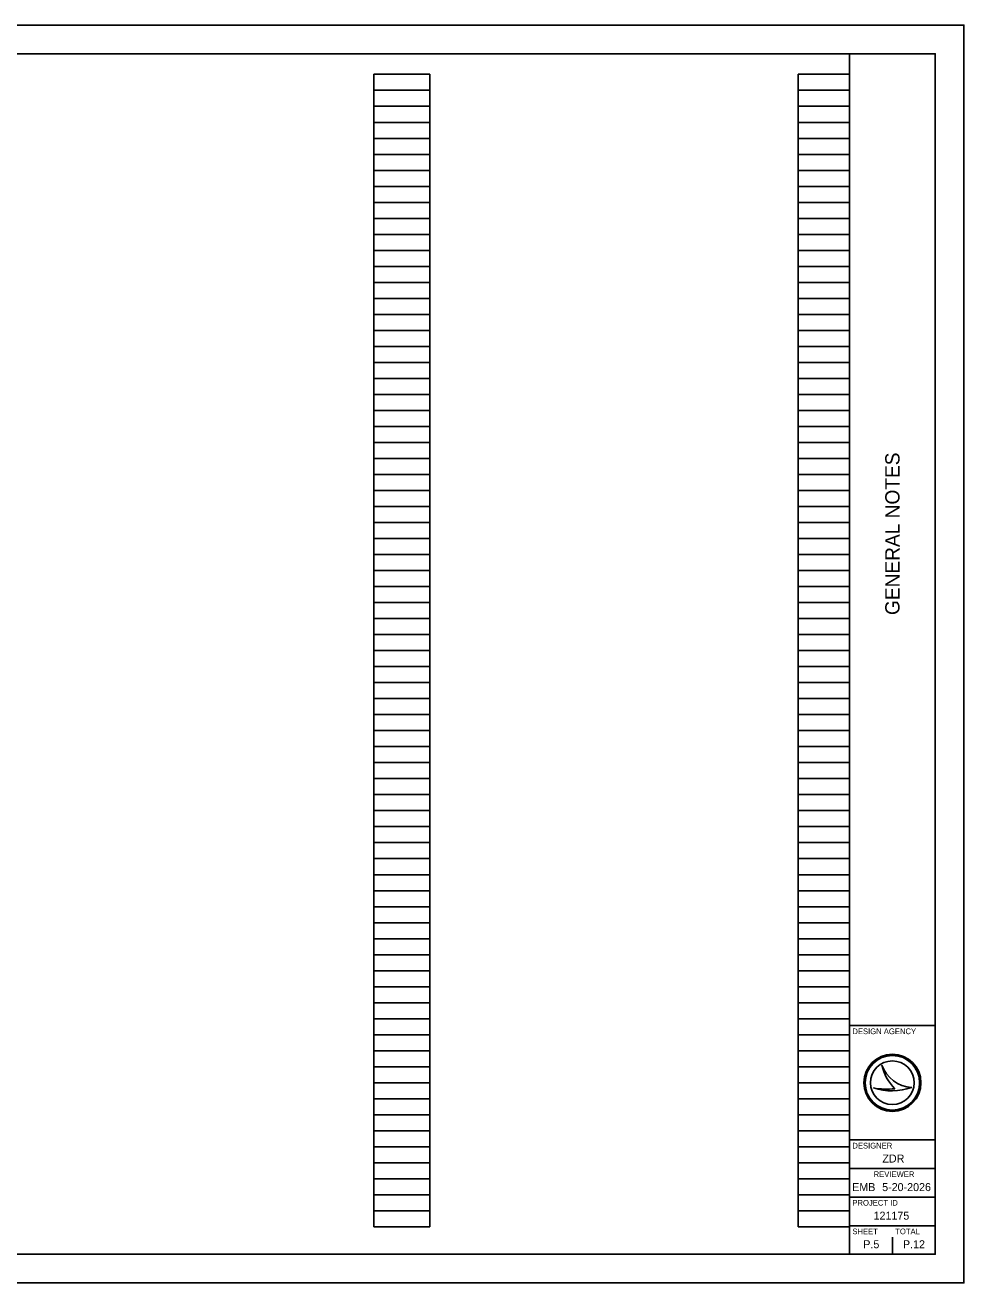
# Model space of a CAD drawing. Extents: x 0 to 34, y 0 to 22.
# Drawn here: x 17.58 to 34, y 0 to 22 of the extents above; entities that cross this region are included whole.
import ezdxf

# ---------------------------------------------------------------- set-up
doc = ezdxf.new("R2010")
doc.units = 0
for name, color, linetype in [('SH_Border', 7, 'Continuous'), ('SH_Cut_Line', 7, 'Continuous'), ('SH_Data', 7, 'Continuous')]:
    doc.layers.add(name, color=color, linetype=linetype)

msp = doc.modelspace()

# ---------------------------------------------------------------- linework, layer by layer
at = {"layer": 'SH_Border'}
for p, q in [((32, 0.5), (32, 21.5)), ((32, 4.5), (33.5, 4.5)), ((32, 2.5), (33.5, 2.5)), ((32, 2), (33.5, 2)), ((32, 1.5), (33.5, 1.5)), ((32, 1), (33.5, 1))]:
    msp.add_line(p, q, dxfattribs=at)
msp.add_lwpolyline([(1.5, 21.5), (33.5, 21.5), (33.5, 0.5), (1.5, 0.5)], close=True, dxfattribs=at)
at = {"layer": 'SH_Cut_Line'}
msp.add_lwpolyline([(0, 0), (34, 0), (34, 22), (0, 22)], close=True, dxfattribs=at)
at = {"layer": 'SH_Data'}
for p, q in [((23.68, 0.98), (23.68, 21.14)), ((23.68, 21.14), (24.66, 21.14)), ((24.66, 0.98), (24.66, 21.14)), ((31.1, 0.98), (31.1, 21.14)), ((31.1, 21.14), (32, 21.14)), ((32, 0.98), (32, 21.14)), ((23.68, 20.86), (24.66, 20.86)), ((31.1, 20.86), (32, 20.86)), ((23.68, 20.58), (24.66, 20.58)), ((31.1, 20.58), (32, 20.58)), ((23.68, 20.3), (24.66, 20.3)), ((31.1, 20.3), (32, 20.3)), ((23.68, 20.02), (24.66, 20.02)), ((31.1, 20.02), (32, 20.02)), ((23.68, 19.74), (24.66, 19.74)), ((31.1, 19.74), (32, 19.74)), ((23.68, 19.46), (24.66, 19.46)), ((31.1, 19.46), (32, 19.46)), ((23.68, 19.18), (24.66, 19.18)), ((31.1, 19.18), (32, 19.18)), ((23.68, 18.9), (24.66, 18.9)), ((31.1, 18.9), (32, 18.9)), ((23.68, 18.62), (24.66, 18.62)), ((31.1, 18.62), (32, 18.62)), ((23.68, 18.34), (24.66, 18.34)), ((31.1, 18.34), (32, 18.34)), ((23.68, 18.06), (24.66, 18.06)), ((31.1, 18.06), (32, 18.06)), ((23.68, 17.78), (24.66, 17.78)), ((31.1, 17.78), (32, 17.78)), ((23.68, 17.5), (24.66, 17.5)), ((31.1, 17.5), (32, 17.5)), ((23.68, 17.22), (24.66, 17.22)), ((31.1, 17.22), (32, 17.22)), ((23.68, 16.94), (24.66, 16.94)), ((31.1, 16.94), (32, 16.94)), ((23.68, 16.66), (24.66, 16.66)), ((31.1, 16.66), (32, 16.66)), ((23.68, 16.38), (24.66, 16.38)), ((31.1, 16.38), (32, 16.38)), ((23.68, 16.1), (24.66, 16.1)), ((31.1, 16.1), (32, 16.1)), ((23.68, 15.82), (24.66, 15.82)), ((31.1, 15.82), (32, 15.82)), ((23.68, 15.54), (24.66, 15.54)), ((31.1, 15.54), (32, 15.54)), ((23.68, 15.26), (24.66, 15.26)), ((31.1, 15.26), (32, 15.26)), ((23.68, 14.98), (24.66, 14.98)), ((31.1, 14.98), (32, 14.98)), ((23.68, 14.7), (24.66, 14.7)), ((31.1, 14.7), (32, 14.7)), ((23.68, 14.42), (24.66, 14.42)), ((31.1, 14.42), (32, 14.42)), ((23.68, 14.14), (24.66, 14.14)), ((31.1, 14.14), (32, 14.14)), ((23.68, 13.86), (24.66, 13.86)), ((31.1, 13.86), (32, 13.86)), ((23.68, 13.58), (24.66, 13.58)), ((31.1, 13.58), (32, 13.58)), ((23.68, 13.3), (24.66, 13.3)), ((31.1, 13.3), (32, 13.3)), ((23.68, 13.02), (24.66, 13.02)), ((31.1, 13.02), (32, 13.02)), ((23.68, 12.74), (24.66, 12.74)), ((31.1, 12.74), (32, 12.74)), ((23.68, 12.46), (24.66, 12.46)), ((31.1, 12.46), (32, 12.46)), ((23.68, 12.18), (24.66, 12.18)), ((31.1, 12.18), (32, 12.18)), ((23.68, 11.9), (24.66, 11.9)), ((31.1, 11.9), (32, 11.9)), ((23.68, 11.62), (24.66, 11.62)), ((31.1, 11.62), (32, 11.62)), ((23.68, 11.34), (24.66, 11.34)), ((31.1, 11.34), (32, 11.34)), ((23.68, 11.06), (24.66, 11.06)), ((31.1, 11.06), (32, 11.06)), ((23.68, 10.78), (24.66, 10.78)), ((31.1, 10.78), (32, 10.78)), ((23.68, 10.5), (24.66, 10.5)), ((31.1, 10.5), (32, 10.5)), ((23.68, 10.22), (24.66, 10.22)), ((31.1, 10.22), (32, 10.22)), ((23.68, 9.94), (24.66, 9.94)), ((31.1, 9.94), (32, 9.94)), ((23.68, 9.66), (24.66, 9.66)), ((31.1, 9.66), (32, 9.66)), ((23.68, 9.38), (24.66, 9.38)), ((31.1, 9.38), (32, 9.38)), ((23.68, 9.1), (24.66, 9.1)), ((31.1, 9.1), (32, 9.1)), ((23.68, 8.82), (24.66, 8.82)), ((31.1, 8.82), (32, 8.82)), ((23.68, 8.54), (24.66, 8.54)), ((31.1, 8.54), (32, 8.54)), ((23.68, 8.26), (24.66, 8.26)), ((31.1, 8.26), (32, 8.26)), ((23.68, 7.98), (24.66, 7.98)), ((31.1, 7.98), (32, 7.98)), ((23.68, 7.7), (24.66, 7.7)), ((31.1, 7.7), (32, 7.7)), ((23.68, 7.42), (24.66, 7.42)), ((31.1, 7.42), (32, 7.42)), ((23.68, 7.14), (24.66, 7.14)), ((31.1, 7.14), (32, 7.14)), ((23.68, 6.86), (24.66, 6.86)), ((31.1, 6.86), (32, 6.86)), ((23.68, 6.58), (24.66, 6.58)), ((31.1, 6.58), (32, 6.58)), ((23.68, 6.3), (24.66, 6.3)), ((31.1, 6.3), (32, 6.3)), ((23.68, 6.02), (24.66, 6.02)), ((31.1, 6.02), (32, 6.02)), ((23.68, 5.74), (24.66, 5.74)), ((31.1, 5.74), (32, 5.74)), ((23.68, 5.46), (24.66, 5.46)), ((31.1, 5.46), (32, 5.46)), ((23.68, 5.18), (24.66, 5.18)), ((31.1, 5.18), (32, 5.18)), ((23.68, 4.9), (24.66, 4.9)), ((31.1, 4.9), (32, 4.9)), ((23.68, 4.62), (24.66, 4.62)), ((31.1, 4.62), (32, 4.62)), ((23.68, 4.34), (24.66, 4.34)), ((31.1, 4.34), (32, 4.34)), ((23.68, 4.06), (24.66, 4.06)), ((31.1, 4.06), (32, 4.06)), ((23.68, 3.78), (24.66, 3.78)), ((31.1, 3.78), (32, 3.78)), ((32.567, 3.81), (32.567, 3.81)), ((23.68, 3.5), (24.66, 3.5)), ((31.1, 3.5), (32, 3.5)), ((32.417, 3.41), (32.417, 3.41)), ((32.75, 3.5), (32.75, 3.5)), ((33.087, 3.419), (33.087, 3.419)), ((23.68, 3.22), (24.66, 3.22)), ((31.1, 3.22), (32, 3.22)), ((23.68, 2.94), (24.66, 2.94)), ((31.1, 2.94), (32, 2.94)), ((23.68, 2.66), (24.66, 2.66)), ((31.1, 2.66), (32, 2.66)), ((23.68, 2.38), (24.66, 2.38)), ((31.1, 2.38), (32, 2.38)), ((23.68, 2.1), (24.66, 2.1)), ((31.1, 2.1), (32, 2.1)), ((23.68, 1.82), (24.66, 1.82)), ((31.1, 1.82), (32, 1.82)), ((23.68, 1.54), (24.66, 1.54)), ((31.1, 1.54), (32, 1.54)), ((23.68, 1.26), (24.66, 1.26)), ((31.1, 1.26), (32, 1.26)), ((23.68, 0.98), (24.66, 0.98)), ((31.1, 0.98), (32, 0.98)), ((32.375, 0.675), (32.375, 0.675)), ((32.75, 0.5), (32.75, 0.8))]:
    msp.add_line(p, q, dxfattribs=at)
for radius in [0.5, 0.477, 0.477, 0.382]:
    msp.add_circle((32.75, 3.5), radius, dxfattribs=at)
for centre, radius, start, end in [((33.116, 3.998), 0.58, 198.9257, 198.9319), ((33.347, 3.97), 0.796, 191.6379, 191.6421), ((33.116, 3.998), 0.58, 198.9319, 267.1657), ((33.347, 3.97), 0.796, 191.6421, 226.0947), ((32.739, 4.37), 1.013, 251.4576, 290.0832), ((32.648, 4.654), 1.266, 259.4964, 259.4995), ((32.739, 4.37), 1.013, 251.4527, 251.4576), ((32.648, 4.654), 1.266, 259.4995, 276.6672)]:
    msp.add_arc(centre, radius, start, end, dxfattribs=at)

# ---------------------------------------------------------------- texts
msp.add_text('GENERAL NOTES', height=0.25, rotation=90, dxfattribs=at).set_placement((32.875, 11.682))
for s, height, p in [('DESIGN AGENCY', 0.1, (32.05, 4.35)), ('DESIGNER', 0.1, (32.05, 2.35)), ('ZDR', 0.14, (32.575, 2.105)), ('REVIEWER', 0.1, (32.422, 1.85)), ('EMB', 0.14, (32.047, 1.605)), ('5-20-2026', 0.14, (32.571, 1.605)), ('PROJECT ID', 0.1, (32.05, 1.35)), ('121175', 0.14, (32.421, 1.105)), ('SHEET', 0.1, (32.05, 0.85)), ('TOTAL', 0.1, (32.8, 0.85)), ('P.5', 0.14, (32.241, 0.605)), ('P.12', 0.14, (32.935, 0.605))]:
    msp.add_text(s, height=height, dxfattribs=at).set_placement(p)

doc.saveas('drawing.dxf')
